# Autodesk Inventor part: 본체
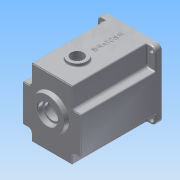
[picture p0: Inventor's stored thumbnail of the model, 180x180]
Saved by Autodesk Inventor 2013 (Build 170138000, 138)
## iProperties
Created: 2016-02
Part Number: 본체
Material: 알루미늄 6061
Document SubType Name: Modeling
Designer: mduedu
Density: 2.71 g/cm^3
Mass: 1343.57 g
Surface Area: 1127.09 cm^2
Volume: 495.782 cm^3
Author: mduedu
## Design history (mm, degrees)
sketch "스케치1"
  geometry: L1 (-47, -47)-(47, -47); L2 (47, -47)-(47, 63); L3 (47, 63)-(-47, 63); L4 (-47, 63)-(-47, -47); 2 further points
  constraints: 8 end point, 2 parallel, 1 horizontal, 1 midpoint, 1 perpendicular, 1 vertical alignment
  dimensions: "d0" = 94 distance of L2.end L3.end; "d155" = 110 distance of L1.end L2.end; "d156" = 47 distance from line of L1 point (0, 0)
extrude "돌출1" new body sketch "스케치1" distance "d2" = 130; taper "d3" = 0 deg
sketch "스케치3"
  geometry: C1 r 40 at (0, 0); 1 further point
  constraints: 1 centre point, 1 coincident
  dimensions: "d9" = 80 diameter of C1
extrude "돌출3" cut sketch "스케치3" distance "d11" = 121; taper "d12" = 0 deg
sketch "스케치4"
  geometry: C1 r 21 at (0, 11); 1 further point
  constraints: 1 centre point, 1 vertical alignment
  dimensions: "d13" = 21 radius of C1; "d15" = 11 distance of point (0, 0) C1.centre
extrude "돌출4" join sketch "스케치4" distance "d16" = 7; taper "d17" = 0 deg
sketch "스케치5"
  geometry: C1 r 15 at (0, -20); 1 further point
  constraints: 1 centre point, 1 vertical alignment
  dimensions: "d18" = 15 radius of C1; "d20" = 20 distance of point (0, 0) C1.centre
extrude "돌출5" join sketch "스케치5" distance "d21" = 7; taper "d22" = 0 deg
sketch "스케치6"
  geometry: C1 r 28 at (0, 11); A1 r 21 centre (0, 11) between (8.978, -7.984) and (-8.978, -7.984) reference; 1 further point
  constraints: 1 centre point, 1 coincident
  dimensions: "d23" = 56 diameter of C1
extrude "돌출6" join sketch "스케치6" distance "d25" = 7; taper "d26" = -10 deg
hole "구멍1" diameter "d29" = 35; stored, may be unused: countersink angle "d33" = 90 deg, drill point angle "d35" = 0 deg; dims "d27" = 10, "d28" = 10, "d30" = 6, "d31" = 4, "d32" = 2, "d34" = 10
hole "구멍2" diameter "d38" = 22; stored, may be unused: countersink angle "d42" = 90 deg, drill point angle "d44" = 0 deg; dims "d36" = 10, "d37" = 10, "d39" = 6, "d40" = 4, "d41" = 2, "d43" = 7
hole "구멍3" diameter "d47" = 19; stored, may be unused: countersink angle "d51" = 90 deg, drill point angle "d53" = 0 deg; dims "d45" = 10, "d46" = 10, "d48" = 6, "d49" = 4, "d50" = 2, "d52" = 1
hole "구멍4" diameter "d56" = 32; stored, may be unused: countersink angle "d60" = 90 deg, drill point angle "d62" = 0 deg; dims "d54" = 10, "d55" = 10, "d57" = 6, "d58" = 4, "d59" = 2, "d61" = 8
hole "구멍5" diameter "d65" = 25; stored, may be unused: countersink angle "d69" = 90 deg, drill point angle "d71" = 0 deg; dims "d63" = 10, "d64" = 10, "d66" = 6, "d67" = 4, "d68" = 2, "d70" = 8
fillet "모깎기2" dims "d73" = 0.3
fillet "모깎기3" dims "d74" = 2
chamfer "모따기1" distance "d75" = 1; stored, may be unused: second distance "d76" = 2, angle "d77" = 45 deg
fillet "모깎기4" dims "d78" = 3
sketch "스케치16"
  geometry: L1 (-23, 32.726)-(23, 32.726); L2 (23, 32.726)-(23, 53); L3 (23, 53)-(-23, 53); L4 (-23, 53)-(-23, 32.726); L5 (-47, 63)-(47, 63) reference; 3 further points
  constraints: 8 end point, 2 parallel, 1 horizontal, 1 midpoint, 1 perpendicular, 1 vertical alignment, 2 other
  dimensions: "d160" = 46 distance of L2.end L3.end; "d163" = 10 distance between parallel lines of L3 L5
extrude "돌출15" cut sketch "스케치16" stored distance "d164" = 10; taper "d165" = 0 deg
fillet "모깎기5" dims "d79" = 2
fillet "모깎기15" dims "d166" = 5
sketch "스케치7"
  geometry: L1 (-23, 48)-(-23, 35.228) reference; L2 (23, 35.228)-(23, 48) reference; L3 (18, 53)-(-18, 53) reference; L4 (47, 63)-(47, -47) reference; L5 (47, -47)-(-47, -47) reference; L6 (-47, -47)-(-47, 63) reference; L7 (-47, 63)-(47, 63) reference; L8 (-26, 48)-(-26, 35.228); L9 (26, 35.228)-(26, 48); L10 (18, 56)-(-18, 56); C1 r 43 at (0, 0); A1 r 5 centre (-18, 48) between (-18, 53) and (-23, 48) reference; A2 r 5 centre (-28, 35.228) between (-24.889, 31.314) and (-23, 35.228) reference; A3 r 40 centre (0, 0) between (-24.889, 31.314) and (24.889, 31.314) reference; A4 r 5 centre (28, 35.228) between (23, 35.228) and (24.889, 31.314) reference; A5 r 5 centre (18, 48) between (23, 48) and (18, 53) reference; A6 r 8 centre (-18, 48) between (-18, 56) and (-26, 48); A7 r 2 centre (-28, 35.228) between (-26.756, 33.662) and (-26, 35.228); A8 r 43 centre (0, 0) between (-26.756, 33.662) and (26.756, 33.662); A9 r 2 centre (28, 35.228) between (26, 35.228) and (26.756, 33.662); A10 r 8 centre (18, 48) between (26, 48) and (18, 56); 1 further point
  constraints: 10 point on circle, 6 centre point, 6 end point, 1 coincident, 7 other
  dimensions: "d80" = 86 diameter of C1; "d167" = 3 distance between parallel lines of L3 L10
extrude "돌출7" cut sketch "스케치7" distance "d83" = 9; taper "d84" = 0 deg
sketch "스케치8" dims "d168" = 36
  geometry: L1 (-36, 4)-(-39.799, 4); L2 (-36, -4)-(-39.799, -4); A1 r 4 centre (-36, 0) between (-36, 4) and (-36, -4); A2 r 40 centre (0, 0) between (-24.889, 31.314) and (24.889, 31.314) reference; A3 r 40 centre (0, 0) between (-39.799, 4) and (-39.799, -4); 2 further points
  constraints: 5 point on circle, 4 end point, 2 centre point, 2 coincident, 2 horizontal alignment, 2 tangent, 1 horizontal, 1 parallel, 2 other
  dimensions: "d169" = 4 radius of A1
extrude "돌출9" join sketch "스케치8" stored distance "d89" = 9; taper "d90" = 0 deg
fillet "모깎기6" dims "d91" = 3.5
sketch "스케치9"
  geometry: L1 (47, 63)-(-47, 63) reference; L2 (47, -47)-(47, 63) reference; L3 (47, 63)-(33, 63); L4 (33, 63)-(33, 30); L5 (33, 30)-(47, 30); L6 (47, 30)-(47, 63); 2 further points
  constraints: 8 end point, 2 parallel, 1 horizontal, 1 perpendicular
  dimensions: "d95" = 33 distance from line of L4 point (0, 0); "d96" = 30 distance from line of L5 point (0, 0)
extrude "돌출10" cut sketch "스케치9" distance "d97" = 120; taper "d98" = 0 deg
sketch "스케치11"
  geometry: L1 (-40, -40)-(40, -40); L2 (40, -40)-(40, 56); L3 (40, 56)-(-40, 56); L4 (-40, 56)-(-40, -40); L5 (-47, -47)-(47, -47) reference; L6 (47, 63)-(-47, 63) reference; L7 (-47, 63)-(-47, -47) reference; C1 r 3.5 at (-40, 56); C2 r 3.5 at (40, 56); C3 r 3.5 at (40, -40); C4 r 3.5 at (-40, -40); 1 further point
  constraints: 8 end point, 4 centre point, 4 coincident, 3 equal radius, 2 parallel, 1 horizontal, 1 perpendicular
  dimensions: "d109" = 80 distance of L2.end L3.end; "d112" = 7 diameter of C1; "d157" = 7 distance from line of L1.start L5; "d158" = 7 distance between parallel lines of L6 L3; "d159" = 7 distance from line of L7 L3.end
extrude "돌출12" cut sketch "스케치11" stored distance "d113" = 63; taper "d114" = 0 deg
fillet "모깎기7" dims "d115" = 8
fillet "모깎기8" dims "d116" = 5
fillet "모깎기11" dims "d119" = 2
fillet "모깎기12" dims "d120" = 2
fillet "모깎기13" dims "d121" = 2
sketch "스케치12"
  geometry: 3 further points
  constraints: 2 horizontal alignment
hole "구멍6" sketch "스케치12" at (36, 0), (-36, 0) diameter "d122" = 3.242; stored, may be unused: countersink angle "d126" = 90 deg, drill point angle "d128" = 120 deg; dims "d123" = 7, "d124" = 4, "d125" = 2, "d127" = 9
sketch "스케치13"
  geometry: L1 (-33, 35)-(-33, 61) reference; L2 (-31, 63)-(31, 63) reference; L3 (33, 61)-(33, 35) reference; L4 (33, -35)-(33, -45) reference; L5 (31, -47)-(-31, -47) reference; L6 (-33, -45)-(-33, -35) reference; L7 (38, 30)-(45, 30) reference; L8 (47, 28)-(47, -28) reference; L9 (45, -30)-(38, -30) reference; L10 (-38, -30)-(-45, -30) reference; L11 (-47, -28)-(-47, 28) reference; L12 (-45, 30)-(-38, 30) reference; L13 (31, 62)-(-31, 62); L14 (-32, 61)-(-32, 35); L15 (-38, 29)-(-45, 29); L16 (-46, 28)-(-46, -28); L17 (-45, -29)-(-38, -29); L18 (-32, -35)-(-32, -45); L19 (-31, -46)-(31, -46); L20 (32, -45)-(32, -35); L21 (38, -29)-(45, -29); L22 (46, -28)-(46, 28); L23 (45, 29)-(38, 29); L24 (32, 35)-(32, 61); L25 (38, 30)-(45, 30) reference; L26 (47, 28)-(47, -28) reference; L27 (45, -30)-(38, -30) reference; L28 (33, -35)-(33, -45) reference; L29 (31, -47)-(-31, -47) reference; L30 (-33, -45)-(-33, -35) reference; L31 (-38, -30)-(-45, -30) reference; L32 (-47, -28)-(-47, 28) reference; L33 (-45, 30)-(-38, 30) reference; L34 (-33, 35)-(-33, 61) reference; L35 (33, 61)-(33, 35) reference; L36 (-31, 63)-(31, 63) reference; C1 r 16 at (0, 11) reference; C2 r 28 at (0, 11) reference; C3 r 16 at (0, 11) reference; C4 r 28 at (0, 11) reference; A1 r 5 centre (-38, 35) between (-38, 30) and (-33, 35) reference; A2 r 2 centre (-31, 61) between (-31, 63) and (-33, 61) reference; A3 r 2 centre (31, 61) between (33, 61) and (31, 63) reference; A4 r 5 centre (38, 35) between (33, 35) and (38, 30) reference; A5 r 5 centre (38, -35) between (38, -30) and (33, -35) reference; A6 r 2 centre (31, -45) between (31, -47) and (33, -45) reference; A7 r 2 centre (-31, -45) between (-33, -45) and (-31, -47) reference; A8 r 5 centre (-38, -35) between (-33, -35) and (-38, -30) reference; A9 r 2 centre (45, 28) between (47, 28) and (45, 30) reference; A10 r 2 centre (45, -28) between (45, -30) and (47, -28) reference; A11 r 2 centre (-45, -28) between (-47, -28) and (-45, -30) reference; A12 r 2 centre (-45, 28) between (-45, 30) and (-47, 28) reference; A13 r 1 centre (-31, 61) between (-31, 62) and (-32, 61); A14 r 6 centre (-38, 35) between (-38, 29) and (-32, 35); A15 r 1 centre (-45, 28) between (-45, 29) and (-46, 28); A16 r 1 centre (-45, -28) between (-46, -28) and (-45, -29); A17 r 6 centre (-38, -35) between (-32, -35) and (-38, -29); A18 r 1 centre (-31, -45) between (-32, -45) and (-31, -46); A19 r 1 centre (31, -45) between (31, -46) and (32, -45); A20 r 6 centre (38, -35) between (38, -29) and (32, -35); A21 r 1 centre (45, -28) between (45, -29) and (46, -28); A22 r 1 centre (45, 28) between (46, 28) and (45, 29); A23 r 6 centre (38, 35) between (32, 35) and (38, 29); A24 r 1 centre (31, 61) between (32, 61) and (31, 62); A25 r 5 centre (38, 35) between (33, 35) and (38, 30) reference; A26 r 2 centre (45, 28) between (47, 28) and (45, 30) reference; A27 r 2 centre (45, -28) between (45, -30) and (47, -28) reference; A28 r 5 centre (38, -35) between (38, -30) and (33, -35) reference; A29 r 2 centre (31, -45) between (31, -47) and (33, -45) reference; A30 r 2 centre (-31, -45) between (-33, -45) and (-31, -47) reference; A31 r 5 centre (-38, -35) between (-33, -35) and (-38, -30) reference; A32 r 2 centre (-45, -28) between (-47, -28) and (-45, -30) reference; A33 r 2 centre (-45, 28) between (-45, 30) and (-47, 28) reference; A34 r 5 centre (-38, 35) between (-38, 30) and (-33, 35) reference; A35 r 2 centre (-31, 61) between (-31, 63) and (-33, 61) reference; A36 r 2 centre (31, 61) between (33, 61) and (31, 63) reference
  constraints: 24 end point, 24 point on circle, 12 centre point, 23 other
  dimensions: "d154" = 1 distance between parallel lines of L13 L2
extrude "돌출13" cut sketch "스케치13" distance "d130" = 1; taper "d131" = 0 deg
fillet "모깎기14" dims "d147" = 0.3
sketch "스케치15"
  geometry: L1 (78, 0)-(0, 0) reference; 3 further points
  constraints: 1 midpoint, 1 vertical alignment, 1 other
  dimensions: "d148" = 40 distance of point (39, -40) point (39, 0)
feature "엠보싱1" sketch "스케치15" dims "d22" = 0, "d149" = 0.5, "d150" = 0
chamfer "모따기4" distance "d151" = 1; stored, may be unused: second distance "d152" = 2, angle "d153" = 45 deg
sketch "스케치17"
  geometry: L1 (39.004, -17.213)-(39.004, -18.809) reference; L2 (39.004, -18.809)-(38.548, -18.809) reference; L3 (38.548, -18.809)-(38.548, -17.213) reference; L4 (38.548, -17.213)-(35.455, -17.213) reference; L5 (35.455, -17.213)-(35.455, -16.822) reference; L6 (35.772, -16.659)-(42.578, -16.659) reference; L7 (42.578, -16.659)-(42.578, -17.213) reference; L8 (42.578, -17.213)-(39.004, -17.213) reference; L9 (38.223, -56.73)-(38.695, -56.73) reference; L10 (38.695, -56.73)-(38.695, -58.073) reference; L11 (38.695, -58.073)-(40.787, -58.073) reference; L12 (40.787, -58.073)-(40.787, -58.643) reference; L13 (40.787, -58.643)-(35.398, -58.643) reference; L14 (35.398, -58.643)-(35.398, -58.277) reference; L15 (35.715, -58.073)-(38.223, -58.073) reference; L16 (38.223, -58.073)-(38.223, -56.73) reference; L17 (41.927, -57.813)-(42.383, -57.813) reference; L18 (42.383, -57.813)-(42.383, -63.031) reference; L19 (42.383, -63.031)-(40.429, -63.031) reference; L20 (40.429, -63.031)-(40.429, -62.608) reference; L21 (40.689, -62.478)-(41.927, -62.478) reference; L22 (41.927, -62.478)-(41.927, -57.813) reference; L23 (36.09, -60.849)-(36.09, -62.624) reference; L24 (36.09, -62.624)-(35.666, -62.624) reference; L25 (35.666, -62.624)-(35.666, -60.849) reference; L26 (35.666, -60.849)-(36.09, -60.849) reference; L27 (37.058, -64.057)-(36.635, -64.057) reference; L28 (36.635, -64.057)-(36.635, -59.539) reference; L29 (36.635, -59.539)-(37.058, -59.539) reference; L30 (37.058, -59.539)-(37.058, -64.057) reference; L31 (42.138, -43.501)-(40.307, -44.168) reference; L32 (40.307, -44.168)-(40.307, -46.871) reference; L33 (40.307, -46.871)-(42.138, -47.555) reference; L34 (42.138, -47.555)-(42.138, -48.133) reference; L35 (42.138, -48.133)-(36.138, -45.853) reference; L36 (36.138, -45.853)-(36.138, -45.202) reference; L37 (36.138, -45.202)-(42.138, -42.923) reference; L38 (42.138, -42.923)-(42.138, -43.501) reference; L39 (36.725, -45.536)-(39.81, -46.684) reference; L40 (39.81, -46.684)-(39.81, -44.364) reference; L41 (39.81, -44.364)-(36.725, -45.536) reference; L42 (40.022, -52.114)-(40.022, -49.94) reference; L43 (40.022, -49.94)-(42.57, -49.94) reference; L44 (42.57, -49.94)-(42.57, -50.494) reference; L45 (42.57, -50.494)-(40.469, -50.494) reference; L46 (40.469, -50.494)-(40.469, -55.094) reference; L47 (40.469, -55.094)-(40.022, -55.094) reference; L48 (40.022, -55.094)-(40.022, -52.659) reference; L49 (40.022, -52.659)-(38.556, -52.659) reference; L50 (38.556, -52.659)-(38.556, -55.973) reference; L51 (38.556, -55.973)-(38.109, -55.973) reference; L52 (38.109, -55.973)-(38.109, -50.73) reference; L53 (36.106, -50.388)-(36.106, -54.955) reference; L54 (36.106, -54.955)-(35.65, -54.955) reference; L55 (35.65, -54.955)-(35.65, -49.81) reference; L56 (38.109, -50.136)-(38.109, -48.768) reference; L57 (38.109, -48.768)-(38.556, -48.768) reference; L58 (38.556, -48.768)-(38.556, -52.114) reference; L59 (38.556, -52.114)-(40.022, -52.114) reference; L60 (36.138, -38.168)-(36.635, -38.168) reference; L61 (36.635, -38.168)-(36.635, -40.041) reference; L62 (36.635, -40.041)-(42.138, -40.041) reference; L63 (42.138, -40.041)-(42.138, -40.586) reference; L64 (42.138, -40.586)-(36.635, -40.586) reference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; C1 r 10 at (39, -89); A1 r 4 centre (4, -12) between (8, -12) and (4, -8) reference; A2 r 4 centre (74, -12) between (74, -8) and (70, -12) reference; 61 further points
  constraints: 2 end point, 1 centre point, 1 midpoint, 1 point on line, 76 other
  dimensions: "d170" = 20 diameter of C1; "d171" = 41 distance from line of C1.centre L110
extrude "돌출16" cut sketch "스케치17" stored distance "d172" = 10; taper "d173" = 0 deg
sketch "스케치18"
  geometry: C1 r 10 at (39, -89) reference; C2 r 15 at (39, -89); 1 further point
  constraints: 1 centre point, 1 coincident
  dimensions: "d174" = 30 diameter of C2
extrude "돌출17" join sketch "스케치18" distance "d175" = 5; taper "d176" = 0 deg
fillet "모깎기16" dims "d177" = 2
sketch "스케치19"
  geometry: C1 r 10 at (18, 80) reference; C2 r 15 at (18, 80); 1 further point
  constraints: 1 centre point, 1 coincident
  dimensions: "d178" = 30 diameter of C2
extrude "돌출18" cut sketch "스케치19" distance "d181" = 5; taper "d182" = 0 deg
chamfer "모따기5" distance "d183" = 0.5; stored, may be unused: second distance "d184" = 2, angle "d185" = 45 deg
node "솔리드1"
pattern_circular "원형 패턴1" dims angle "d93" = 360 deg
mirror "대칭1"
mirror "대칭2"
node "절단 모서리 투영1"
node "절단 모서리 투영2"
node "절단 모서리 투영3"
node "절단 모서리 투영4"
